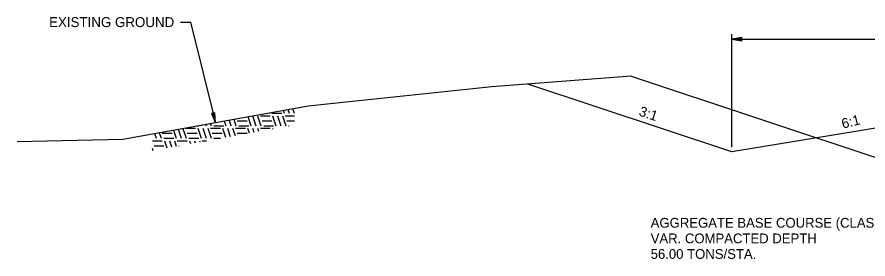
# Model space of a CAD drawing. Extents: x 1824008 to 1828864, y 689441 to 689870.
# Drawn here: x 1828711.2 to 1828762.4, y 689782.5 to 689797.1 of the extents above; entities that cross this region are included whole.
import ezdxf

# ---------------------------------------------------------------- set-up
doc = ezdxf.new("R2010")
doc.units = 0
for name, color, linetype in [('1', 7, 'Continuous'), ('19', 7, 'Continuous'), ('R_Draft', 7, 'Continuous')]:
    doc.layers.add(name, color=color, linetype=linetype)

msp = doc.modelspace()

# ---------------------------------------------------------------- linework, layer by layer
at = {"layer": '1'}
for p, q in [((1828754.22, 689789.201), (1828754.22, 689796.017)), ((1828754.82, 689795.822), (1828754.22, 689795.717)), ((1828754.22, 689795.717), (1828774.22, 689795.717)), ((1828754.22, 689795.717), (1828754.82, 689795.612)), ((1828754.82, 689795.767), (1828754.38, 689795.732)), ((1828754.38, 689795.702), (1828754.82, 689795.662)), ((1828754.82, 689795.612), (1828754.82, 689795.822)), ((1828748.155, 689793.481), (1828765.008, 689787.863)), ((1828754.22, 689788.919), (1828741.942, 689793.012)), ((1828727.286, 689791.229), (1828727.223, 689791.416)), ((1828727.286, 689791.229), (1828727.223, 689791.416)), ((1828727.286, 689791.229), (1828727.223, 689791.416)), ((1828727.586, 689791.229), (1828727.506, 689791.468)), ((1828727.586, 689791.229), (1828727.506, 689791.468)), ((1828727.586, 689791.229), (1828727.506, 689791.468)), ((1828727.883, 689791.238), (1828727.789, 689791.519)), ((1828727.883, 689791.238), (1828727.789, 689791.519)), ((1828727.883, 689791.238), (1828727.789, 689791.519)), ((1828723.09, 689791.282), (1828722.888, 689791.231)), ((1828722.888, 689791.231), (1828723.134, 689790.675)), ((1828722.933, 689791.239), (1828723.08, 689790.827)), ((1828723.105, 689790.831), (1828723.039, 689791.264)), ((1828723.134, 689790.675), (1828723.09, 689791.282)), ((1828724.086, 689790.479), (1828723.97, 689790.826)), ((1828724.086, 689790.479), (1828723.97, 689790.826)), ((1828724.086, 689790.479), (1828723.97, 689790.826)), ((1828724.386, 689790.479), (1828724.253, 689790.878)), ((1828724.386, 689790.479), (1828724.253, 689790.878)), ((1828724.386, 689790.479), (1828724.253, 689790.878)), ((1828725.286, 689790.479), (1828725.101, 689791.032)), ((1828725.286, 689790.479), (1828725.101, 689791.032)), ((1828725.286, 689790.479), (1828725.101, 689791.032)), ((1828725.586, 689790.479), (1828725.386, 689791.079)), ((1828725.586, 689790.479), (1828725.386, 689791.079)), ((1828725.586, 689790.479), (1828725.386, 689791.079)), ((1828725.886, 689790.479), (1828725.686, 689791.079)), ((1828725.886, 689790.479), (1828725.686, 689791.079)), ((1828725.886, 689790.479), (1828725.686, 689791.079)), ((1828726.436, 689791.079), (1828725.836, 689791.079)), ((1828726.436, 689791.079), (1828725.836, 689791.079)), ((1828726.436, 689791.079), (1828725.836, 689791.079)), ((1828726.386, 689791.229), (1828726.374, 689791.262)), ((1828726.386, 689791.229), (1828726.374, 689791.262)), ((1828726.386, 689791.229), (1828726.374, 689791.262)), ((1828727.136, 689791.229), (1828726.536, 689791.229)), ((1828727.136, 689791.229), (1828726.536, 689791.229)), ((1828727.136, 689791.229), (1828726.536, 689791.229)), ((1828726.786, 689790.479), (1828726.586, 689791.079)), ((1828726.786, 689790.479), (1828726.586, 689791.079)), ((1828726.786, 689790.479), (1828726.586, 689791.079)), ((1828727.086, 689790.479), (1828726.886, 689791.079)), ((1828727.086, 689790.479), (1828726.886, 689791.079)), ((1828727.086, 689790.479), (1828726.886, 689791.079)), ((1828727.386, 689790.479), (1828727.186, 689791.079)), ((1828727.386, 689790.479), (1828727.186, 689791.079)), ((1828727.386, 689790.479), (1828727.186, 689791.079)), ((1828727.386, 689791.079), (1828727.336, 689791.079)), ((1828727.386, 689791.079), (1828727.336, 689791.079)), ((1828727.386, 689791.079), (1828727.336, 689791.079)), ((1828727.883, 689791.079), (1828727.386, 689791.079)), ((1828727.883, 689791.079), (1828727.386, 689791.079)), ((1828727.883, 689791.079), (1828727.386, 689791.079)), ((1828721.386, 689789.729), (1828721.188, 689790.322)), ((1828721.386, 689789.729), (1828721.188, 689790.322)), ((1828721.386, 689789.729), (1828721.188, 689790.322)), ((1828721.386, 689790.329), (1828721.336, 689790.329)), ((1828721.386, 689790.329), (1828721.336, 689790.329)), ((1828721.386, 689790.329), (1828721.336, 689790.329)), ((1828721.936, 689790.329), (1828721.386, 689790.329)), ((1828721.936, 689790.329), (1828721.386, 689790.329)), ((1828721.936, 689790.329), (1828721.386, 689790.329)), ((1828722.136, 689790.479), (1828722.053, 689790.479)), ((1828722.136, 689790.479), (1828722.053, 689790.479)), ((1828722.136, 689790.479), (1828722.053, 689790.479)), ((1828722.286, 689789.729), (1828722.086, 689790.329)), ((1828722.286, 689789.729), (1828722.086, 689790.329)), ((1828722.286, 689789.729), (1828722.086, 689790.329)), ((1828722.286, 689790.479), (1828722.272, 689790.519)), ((1828722.286, 689790.479), (1828722.272, 689790.519)), ((1828722.286, 689790.479), (1828722.272, 689790.519)), ((1828722.586, 689789.729), (1828722.386, 689790.329)), ((1828722.586, 689789.729), (1828722.386, 689790.329)), ((1828722.586, 689789.729), (1828722.386, 689790.329)), ((1828722.586, 689790.479), (1828722.555, 689790.57)), ((1828722.586, 689790.479), (1828722.555, 689790.57)), ((1828722.586, 689790.479), (1828722.555, 689790.57)), ((1828722.886, 689789.729), (1828722.686, 689790.329)), ((1828722.886, 689789.729), (1828722.686, 689790.329)), ((1828722.886, 689789.729), (1828722.686, 689790.329)), ((1828723.436, 689790.329), (1828722.836, 689790.329)), ((1828723.436, 689790.329), (1828722.836, 689790.329)), ((1828723.436, 689790.329), (1828722.836, 689790.329)), ((1828722.886, 689790.479), (1828722.838, 689790.621)), ((1828722.886, 689790.479), (1828722.838, 689790.621)), ((1828722.886, 689790.479), (1828722.838, 689790.621)), ((1828723.636, 689790.479), (1828723.036, 689790.479)), ((1828723.636, 689790.479), (1828723.036, 689790.479)), ((1828723.636, 689790.479), (1828723.036, 689790.479)), ((1828723.765, 689789.789), (1828723.586, 689790.329)), ((1828723.765, 689789.789), (1828723.586, 689790.329)), ((1828723.765, 689789.789), (1828723.586, 689790.329)), ((1828723.786, 689790.479), (1828723.687, 689790.775)), ((1828723.786, 689790.479), (1828723.687, 689790.775)), ((1828723.786, 689790.479), (1828723.687, 689790.775)), ((1828724.048, 689789.841), (1828723.886, 689790.329)), ((1828724.048, 689789.841), (1828723.886, 689790.329)), ((1828724.048, 689789.841), (1828723.886, 689790.329)), ((1828724.331, 689789.892), (1828724.186, 689790.329)), ((1828724.331, 689789.892), (1828724.186, 689790.329)), ((1828724.331, 689789.892), (1828724.186, 689790.329)), ((1828724.386, 689790.329), (1828724.336, 689790.329)), ((1828724.386, 689790.329), (1828724.336, 689790.329)), ((1828724.386, 689790.329), (1828724.336, 689790.329)), ((1828724.936, 689790.329), (1828724.386, 689790.329)), ((1828724.936, 689790.329), (1828724.386, 689790.329)), ((1828724.936, 689790.329), (1828724.386, 689790.329)), ((1828725.036, 689790.779), (1828724.436, 689790.779)), ((1828725.036, 689790.779), (1828724.436, 689790.779)), ((1828725.036, 689790.779), (1828724.436, 689790.779)), ((1828725.136, 689790.479), (1828724.536, 689790.479)), ((1828725.136, 689790.479), (1828724.536, 689790.479)), ((1828725.136, 689790.479), (1828724.536, 689790.479)), ((1828725.18, 689790.046), (1828725.086, 689790.329)), ((1828725.18, 689790.046), (1828725.086, 689790.329)), ((1828725.18, 689790.046), (1828725.086, 689790.329)), ((1828725.463, 689790.097), (1828725.386, 689790.329)), ((1828725.463, 689790.097), (1828725.386, 689790.329)), ((1828725.463, 689790.097), (1828725.386, 689790.329)), ((1828725.746, 689790.148), (1828725.686, 689790.329)), ((1828725.746, 689790.148), (1828725.686, 689790.329)), ((1828725.746, 689790.148), (1828725.686, 689790.329)), ((1828726.436, 689790.329), (1828725.836, 689790.329)), ((1828726.436, 689790.329), (1828725.836, 689790.329)), ((1828726.436, 689790.329), (1828725.836, 689790.329)), ((1828726.536, 689790.779), (1828725.936, 689790.779)), ((1828726.536, 689790.779), (1828725.936, 689790.779)), ((1828726.536, 689790.779), (1828725.936, 689790.779)), ((1828726.636, 689790.479), (1828726.036, 689790.479)), ((1828726.636, 689790.479), (1828726.036, 689790.479)), ((1828726.636, 689790.479), (1828726.036, 689790.479)), ((1828726.594, 689790.302), (1828726.586, 689790.329)), ((1828726.594, 689790.302), (1828726.586, 689790.329)), ((1828726.594, 689790.302), (1828726.586, 689790.329)), ((1828727.883, 689790.779), (1828727.436, 689790.779)), ((1828727.883, 689790.779), (1828727.436, 689790.779)), ((1828727.883, 689790.779), (1828727.436, 689790.779)), ((1828727.568, 689790.479), (1828727.536, 689790.479)), ((1828727.568, 689790.479), (1828727.536, 689790.479)), ((1828727.568, 689790.479), (1828727.536, 689790.479)), ((1828719.586, 689789.729), (1828719.49, 689790.014)), ((1828719.586, 689789.729), (1828719.49, 689790.014)), ((1828719.586, 689789.729), (1828719.49, 689790.014)), ((1828719.886, 689789.729), (1828719.773, 689790.065)), ((1828719.886, 689789.729), (1828719.773, 689790.065)), ((1828719.886, 689789.729), (1828719.773, 689790.065)), ((1828720.536, 689790.029), (1828719.936, 689790.029)), ((1828720.536, 689790.029), (1828719.936, 689790.029)), ((1828720.536, 689790.029), (1828719.936, 689790.029)), ((1828720.786, 689789.729), (1828720.622, 689790.219)), ((1828720.786, 689789.729), (1828720.622, 689790.219)), ((1828720.786, 689789.729), (1828720.622, 689790.219)), ((1828721.086, 689789.729), (1828720.905, 689790.271)), ((1828721.086, 689789.729), (1828720.905, 689790.271)), ((1828721.086, 689789.729), (1828720.905, 689790.271)), ((1828722.036, 689790.029), (1828721.436, 689790.029)), ((1828722.036, 689790.029), (1828721.436, 689790.029)), ((1828722.036, 689790.029), (1828721.436, 689790.029)), ((1828723.536, 689790.029), (1828722.936, 689790.029)), ((1828723.536, 689790.029), (1828722.936, 689790.029)), ((1828723.536, 689790.029), (1828722.936, 689790.029)), ((1828725.036, 689790.029), (1828724.436, 689790.029)), ((1828725.036, 689790.029), (1828724.436, 689790.029)), ((1828725.036, 689790.029), (1828724.436, 689790.029)), ((1828719.936, 689789.579), (1828719.336, 689789.579)), ((1828719.936, 689789.579), (1828719.336, 689789.579)), ((1828719.936, 689789.579), (1828719.336, 689789.579)), ((1828720.036, 689789.279), (1828719.436, 689789.279)), ((1828720.036, 689789.279), (1828719.436, 689789.279)), ((1828720.036, 689789.279), (1828719.436, 689789.279)), ((1828720.636, 689789.729), (1828720.036, 689789.729)), ((1828720.636, 689789.729), (1828720.036, 689789.729)), ((1828720.636, 689789.729), (1828720.036, 689789.729)), ((1828720.229, 689789.148), (1828720.086, 689789.579)), ((1828720.229, 689789.148), (1828720.086, 689789.579)), ((1828720.229, 689789.148), (1828720.086, 689789.579)), ((1828720.512, 689789.199), (1828720.386, 689789.579)), ((1828720.512, 689789.199), (1828720.386, 689789.579)), ((1828720.512, 689789.199), (1828720.386, 689789.579)), ((1828720.795, 689789.251), (1828720.686, 689789.579)), ((1828720.795, 689789.251), (1828720.686, 689789.579)), ((1828720.795, 689789.251), (1828720.686, 689789.579)), ((1828721.386, 689789.579), (1828720.836, 689789.579)), ((1828721.386, 689789.579), (1828720.836, 689789.579)), ((1828721.386, 689789.579), (1828720.836, 689789.579)), ((1828720.95, 689789.279), (1828720.936, 689789.279)), ((1828720.95, 689789.279), (1828720.936, 689789.279)), ((1828720.95, 689789.279), (1828720.936, 689789.279)), ((1828721.436, 689789.579), (1828721.386, 689789.579)), ((1828721.436, 689789.579), (1828721.386, 689789.579)), ((1828721.436, 689789.579), (1828721.386, 689789.579)), ((1828722.136, 689789.729), (1828721.536, 689789.729)), ((1828722.136, 689789.729), (1828721.536, 689789.729)), ((1828722.136, 689789.729), (1828721.536, 689789.729)), ((1828721.644, 689789.405), (1828721.586, 689789.579)), ((1828721.644, 689789.405), (1828721.586, 689789.579)), ((1828721.644, 689789.405), (1828721.586, 689789.579)), ((1828721.927, 689789.456), (1828721.886, 689789.579)), ((1828721.927, 689789.456), (1828721.886, 689789.579)), ((1828721.927, 689789.456), (1828721.886, 689789.579)), ((1828722.209, 689789.507), (1828722.186, 689789.579)), ((1828722.209, 689789.507), (1828722.186, 689789.579)), ((1828722.209, 689789.507), (1828722.186, 689789.579)), ((1828722.604, 689789.579), (1828722.336, 689789.579)), ((1828722.604, 689789.579), (1828722.336, 689789.579)), ((1828722.604, 689789.579), (1828722.336, 689789.579)), ((1828723.431, 689789.729), (1828723.036, 689789.729)), ((1828723.431, 689789.729), (1828723.036, 689789.729)), ((1828723.431, 689789.729), (1828723.036, 689789.729)), ((1828719.38, 689788.994), (1828719.336, 689789.127)), ((1828719.38, 689788.994), (1828719.336, 689789.127)), ((1828719.38, 689788.994), (1828719.336, 689789.127))]:
    msp.add_line(p, q, dxfattribs=at)
for points in [[(1828721.022, 689796.748), (1828721.622, 689796.748), (1828723.134, 689790.675)], [(1828748.155, 689793.481), (1828739.772, 689792.848), (1828728.716, 689791.687), (1828717.551, 689789.663), (1828711.19, 689789.527)]]:
    msp.add_lwpolyline(points, dxfattribs=at)
at = {"layer": '19'}
msp.add_line((1828770.22, 689791.586), (1828754.22, 689788.919), dxfattribs=at)
at = {"layer": 'R_Draft'}
for p, q in [((1828727.286, 689791.229), (1828727.223, 689791.416)), ((1828727.586, 689791.229), (1828727.506, 689791.468)), ((1828727.883, 689791.238), (1828727.789, 689791.519)), ((1828724.086, 689790.479), (1828723.97, 689790.826)), ((1828724.386, 689790.479), (1828724.253, 689790.878)), ((1828725.286, 689790.479), (1828725.101, 689791.032)), ((1828725.586, 689790.479), (1828725.386, 689791.079)), ((1828725.886, 689790.479), (1828725.686, 689791.079)), ((1828726.436, 689791.079), (1828725.836, 689791.079)), ((1828726.386, 689791.229), (1828726.374, 689791.262)), ((1828727.136, 689791.229), (1828726.536, 689791.229)), ((1828726.786, 689790.479), (1828726.586, 689791.079)), ((1828727.086, 689790.479), (1828726.886, 689791.079)), ((1828727.386, 689790.479), (1828727.186, 689791.079)), ((1828727.386, 689791.079), (1828727.336, 689791.079)), ((1828727.883, 689791.079), (1828727.386, 689791.079)), ((1828721.386, 689789.729), (1828721.188, 689790.322)), ((1828721.386, 689790.329), (1828721.336, 689790.329)), ((1828721.936, 689790.329), (1828721.386, 689790.329)), ((1828722.136, 689790.479), (1828722.053, 689790.479)), ((1828722.286, 689789.729), (1828722.086, 689790.329)), ((1828722.286, 689790.479), (1828722.272, 689790.519)), ((1828722.586, 689789.729), (1828722.386, 689790.329)), ((1828722.586, 689790.479), (1828722.555, 689790.57)), ((1828722.886, 689789.729), (1828722.686, 689790.329)), ((1828723.436, 689790.329), (1828722.836, 689790.329)), ((1828722.886, 689790.479), (1828722.838, 689790.621)), ((1828723.636, 689790.479), (1828723.036, 689790.479)), ((1828723.765, 689789.789), (1828723.586, 689790.329)), ((1828723.786, 689790.479), (1828723.687, 689790.775)), ((1828724.048, 689789.841), (1828723.886, 689790.329)), ((1828724.331, 689789.892), (1828724.186, 689790.329)), ((1828724.386, 689790.329), (1828724.336, 689790.329)), ((1828724.936, 689790.329), (1828724.386, 689790.329)), ((1828725.036, 689790.779), (1828724.436, 689790.779)), ((1828725.136, 689790.479), (1828724.536, 689790.479)), ((1828725.18, 689790.046), (1828725.086, 689790.329)), ((1828725.463, 689790.097), (1828725.386, 689790.329)), ((1828725.746, 689790.148), (1828725.686, 689790.329)), ((1828726.436, 689790.329), (1828725.836, 689790.329)), ((1828726.536, 689790.779), (1828725.936, 689790.779)), ((1828726.636, 689790.479), (1828726.036, 689790.479)), ((1828726.594, 689790.302), (1828726.586, 689790.329)), ((1828727.883, 689790.779), (1828727.436, 689790.779)), ((1828727.568, 689790.479), (1828727.536, 689790.479)), ((1828719.586, 689789.729), (1828719.49, 689790.014)), ((1828719.886, 689789.729), (1828719.773, 689790.065)), ((1828720.536, 689790.029), (1828719.936, 689790.029)), ((1828720.786, 689789.729), (1828720.622, 689790.219)), ((1828721.086, 689789.729), (1828720.905, 689790.271)), ((1828722.036, 689790.029), (1828721.436, 689790.029)), ((1828723.536, 689790.029), (1828722.936, 689790.029)), ((1828725.036, 689790.029), (1828724.436, 689790.029)), ((1828719.936, 689789.579), (1828719.336, 689789.579)), ((1828720.036, 689789.279), (1828719.436, 689789.279)), ((1828720.636, 689789.729), (1828720.036, 689789.729)), ((1828720.229, 689789.148), (1828720.086, 689789.579)), ((1828720.512, 689789.199), (1828720.386, 689789.579)), ((1828720.795, 689789.251), (1828720.686, 689789.579)), ((1828721.386, 689789.579), (1828720.836, 689789.579)), ((1828720.95, 689789.279), (1828720.936, 689789.279)), ((1828721.436, 689789.579), (1828721.386, 689789.579)), ((1828722.136, 689789.729), (1828721.536, 689789.729)), ((1828721.644, 689789.405), (1828721.586, 689789.579)), ((1828721.927, 689789.456), (1828721.886, 689789.579)), ((1828722.209, 689789.507), (1828722.186, 689789.579)), ((1828722.604, 689789.579), (1828722.336, 689789.579)), ((1828723.431, 689789.729), (1828723.036, 689789.729)), ((1828719.38, 689788.994), (1828719.336, 689789.127))]:
    msp.add_line(p, q, dxfattribs=at)

# ---------------------------------------------------------------- texts
at = {"layer": '1'}
for s, rotation, p in [('3:1', 341.5651, (1828748.575, 689791.126)), ('6:1', 14.0362, (1828760.899, 689790.322))]:
    msp.add_text(s, height=0.6, rotation=rotation, dxfattribs=at).set_placement(p)
at = {"layer": '19'}
for s, p in [('AGGREGATE BASE COURSE (CLASS 7)', (1828749.327, 689784.354)), ('VAR. COMPACTED DEPTH', (1828749.327, 689783.414)), ('56.00 TONS/STA.', (1828749.327, 689782.474))]:
    msp.add_text(s, height=0.59001, rotation=360, dxfattribs=at).set_placement(p)
at = {"layer": 'R_Draft'}
msp.add_text('EXISTING GROUND', height=0.6, dxfattribs=at).set_placement((1828713.12, 689796.448))

doc.saveas('drawing.dxf')
